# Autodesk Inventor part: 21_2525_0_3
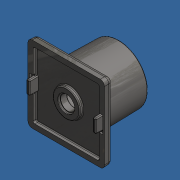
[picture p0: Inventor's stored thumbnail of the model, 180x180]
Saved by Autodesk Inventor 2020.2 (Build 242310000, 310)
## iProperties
Part Number: 21_2525_0_3
Material: ABS Plastic
Document SubType Name: Modeling
Designer: amoles
Appearance: Smooth - White
Mass: 14.4721 g
Surface Area: 102.404 cm^2
Volume: 13.653 cm^3
Density: 1.06 g/cm^3
Author: amoles
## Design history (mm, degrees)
feature "Base1"
body "Solid1"
